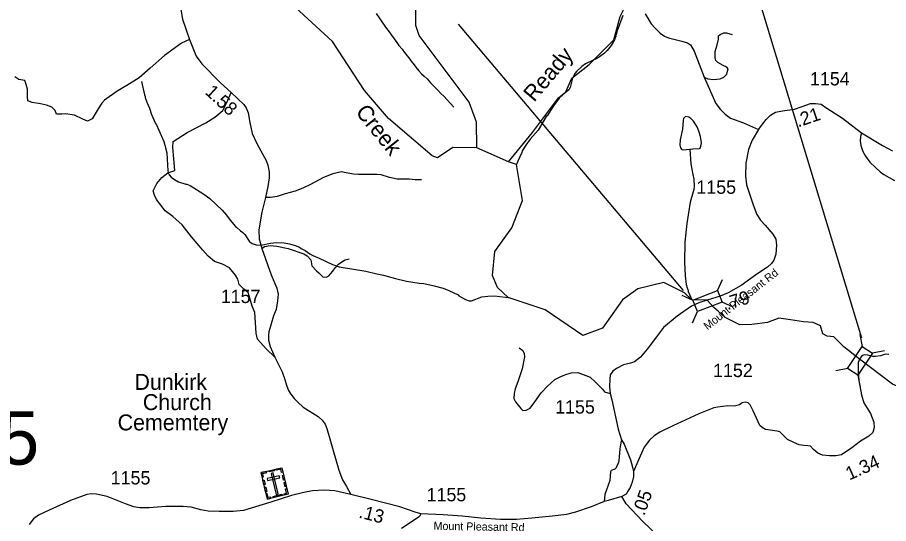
# Model space of a CAD drawing. Extents: x 1248224 to 1454986, y 825081 to 985870.
# Drawn here: x 1300002 to 1308169, y 872533 to 877278 of the extents above; entities that cross this region are included whole.
import ezdxf

# ---------------------------------------------------------------- set-up
doc = ezdxf.new("R2010")
doc.units = 0
for name, color, linetype in [('Exist Cultural Cemetery CELL', 7, 'Continuous'), ('Exist Cultural Church Label', 7, 'Continuous'), ('Exist Hydrographic Creek Single Shore', 7, 'Continuous'), ('Exist Hydrographic Misc Water Feature', 7, 'Continuous'), ('Exist Road Non-System Type 51', 7, 'Continuous'), ('Exist Road Secondary Mileage Hundredths English Label', 7, 'Continuous'), ('Exist Road Secondary Structure Standard Bridge CELL', 7, 'Continuous'), ('Exist Road Secondary Structure Standard Bridge Number Label', 7, 'Continuous'), ('Exist Road Secondary Type 41 Attributed', 7, 'Continuous'), ('Exist Road Secondary Type 51 Attributed', 7, 'Continuous'), ('Exist Road Secondary Type 51 Label', 7, 'Continuous'), ('Exist Road Secondary Type 51 Number Label', 7, 'Continuous')]:
    doc.layers.add(name, color=color, linetype=linetype)

msp = doc.modelspace()

# ---------------------------------------------------------------- linework, layer by layer
at = {"layer": 'Exist Cultural Cemetery CELL'}
for points in [[(1302286.7, 873011), (1302480.3, 873057.3), (1302539.5, 872809.6), (1302345.9, 872763.3)], [(1302296.8, 872968.8), (1302307.8, 872971.5), (1302300.3, 873002.8), (1302339.8, 873012.2), (1302337.2, 873023), (1302286.7, 873011)], [(1302358.7, 873028.2), (1302409.1, 873040.2), (1302411.8, 873029.1), (1302361.4, 873017.1)], [(1302490.5, 873015.1), (1302479.4, 873012.5), (1302472, 873043.8), (1302432.5, 873034.3), (1302429.9, 873045.2), (1302480.4, 873057.2)], [(1302314, 872896.7), (1302303.9, 872938.8), (1302315, 872941.5), (1302325.1, 872899.4)], [(1302342.2, 872954.3), (1302346.6, 872936.1), (1302461.1, 872963.5), (1302456.7, 872981.6)], [(1302399.5, 873007.8), (1302381.4, 873003.5), (1302428.5, 872806.2), (1302446.7, 872810.6)], [(1302496.4, 872941.4), (1302486.3, 872983.5), (1302497.4, 872986.1), (1302507.4, 872944)], [(1302329.6, 872831.3), (1302319.5, 872873.5), (1302330.6, 872876.1), (1302340.7, 872834)], [(1302511.7, 872877.3), (1302501.6, 872919.4), (1302512.7, 872922), (1302522.8, 872879.9)], [(1302507.3, 872801.9), (1302504.6, 872813.1), (1302526, 872818.2), (1302516.6, 872857.5), (1302527.5, 872860.1), (1302539.5, 872809.6)], [(1302378.1, 872771.1), (1302375.4, 872782.2), (1302354, 872777.1), (1302344.6, 872816.4), (1302333.8, 872813.8), (1302345.8, 872763.3)], [(1302399.1, 872787.8), (1302481.7, 872807.6), (1302484.3, 872796.5), (1302401.8, 872776.8)]]:
    msp.add_lwpolyline(points, close=True, dxfattribs=at)
at = {"layer": 'Exist Hydrographic Creek Single Shore'}
for points in [[(1304607.2, 875923.4), (1304830.5, 876199), (1305073.4, 876522.9), (1305142.8, 876580.8), (1305200.7, 876708), (1305362.6, 876835.2), (1305593.9, 877066.6), (1305651.8, 877286.4), (1305744.3, 877471.4), (1305779, 877598.7), (1305779, 877760.6), (1305755.9, 878142.3), (1305755.9, 878558.8), (1305755.9, 878778.5), (1305721.2, 878975.2), (1305721.2, 879160.2), (1305686.5, 879356.9), (1305686.5, 879484.1), (1305744.3, 879831.1), (1305813.7, 880050.9), (1305871.6, 880270.7)], [(1304309.1, 876054.1), (1304084.2, 876058.7), (1303941.2, 875963), (1303891.1, 875980.4), (1303482.2, 876330.1), (1303255.2, 876594), (1302957.1, 877053), (1302532, 877445.5)], [(1306636.7, 874466.4), (1306571.6, 874523.3), (1306531.5, 874558.9), (1306468.8, 874627.1), (1306326.2, 874631), (1306255, 874695.2), (1306062.6, 874794.1), (1305818.9, 874733.2), (1305674, 874629.3), (1305485.9, 874363.9), (1305302.5, 874297.6), (1304950.2, 874537.8), (1304602.2, 874653), (1304504.1, 874747), (1304457.2, 874859.5), (1304479.2, 875082.3), (1304638, 875304.6), (1304736.1, 875560.8), (1304680.5, 875899.4), (1304607.2, 875923.4), (1304309.1, 876054.1)], [(1307897, 874073.3), (1307748.2, 874188.6), (1307654.5, 874282.4), (1307594.8, 874291.6), (1307552.7, 874313.1), (1307532.3, 874386.3), (1307460.9, 874419.2), (1307372.8, 874425.7), (1307249.3, 874442.4), (1307138.8, 874458.8), (1307033.4, 874417.6), (1306886.8, 874399.5), (1306773.2, 874397.8), (1306636.7, 874466.4)], [(1309154.5, 873303.6), (1309141.3, 873330.9), (1308897.3, 873588.6), (1308830.3, 873606.4), (1308585.6, 873596.3), (1308575.8, 873602.6), (1308466.6, 873740.7), (1308388.7, 873762), (1308206.5, 873839.3), (1307897, 874073.3)]]:
    msp.add_lwpolyline(points, dxfattribs=at)
at = {"layer": 'Exist Hydrographic Misc Water Feature'}
for points in [[(1304309.1, 876054.1), (1304307.2, 876297.2), (1304236.1, 876482.4), (1303767.1, 877109), (1303736.1, 877201.5), (1303743.1, 877867.7), (1303674.1, 878479.7), (1303649.1, 878503.2), (1303651.1, 878588.5), (1303589.1, 878763.8), (1303637.1, 879396.4), (1303337.6, 879538.2), (1303277.1, 879679.4), (1303282, 879895.9), (1303361.1, 880094.6), (1303645.1, 880463.1), (1303932, 880956.4), (1304359.1, 881397.5)], [(1305677.6, 877295.2), (1305625.6, 877152.8), (1305616.5, 877115.1), (1305610.3, 877109.2), (1305612.1, 877101.2), (1305599.2, 877069.5), (1305567.7, 877014.5), (1305530.3, 876967.6), (1305505.6, 876944.4), (1305458.6, 876907.7), (1305440.2, 876896.3), (1305326.7, 876841.5), (1305294, 876818.5), (1305244.7, 876771.9), (1305232.2, 876756.3), (1305206.9, 876709.1), (1305184.4, 876621.7), (1305171.8, 876598.1), (1305114.4, 876551.8), (1305081.6, 876520.7), (1305027.6, 876450.3), (1304968.9, 876356.1), (1304960.7, 876348.3), (1304885, 876222.5), (1304810.6, 876136.7), (1304769.1, 876081.9), (1304735.6, 876026.9), (1304731.1, 876011.1), (1304692.8, 875932.1), (1304680.5, 875899.4)], [(1301164.4, 876677.9), (1301192.9, 876553.1), (1301200.5, 876536.9), (1301200.2, 876528.9), (1301214.9, 876484.5), (1301239.3, 876427.8), (1301259.7, 876367.2), (1301295.4, 876284.2), (1301304.9, 876269.9), (1301327.6, 876221.3), (1301374.7, 876116.1), (1301385.6, 876079.7), (1301401.6, 876007.3), (1301412.9, 875839), (1301418.2, 875814.8), (1301425.9, 875802.6), (1301443.4, 875782.1), (1301474.6, 875757.2), (1301514, 875736.1), (1301581.5, 875714.2), (1301589.5, 875713.9), (1301621.1, 875701), (1301750.9, 875621.3), (1301805.8, 875579.7), (1301922.8, 875472.4), (1301963.5, 875423.2), (1301996.2, 875376.3), (1302046.5, 875316.9), (1302060.3, 875308.5), (1302093.4, 875277.5), (1302116.9, 875260.8), (1302134.4, 875242.3), (1302174.7, 875181.2), (1302182.5, 875172.9), (1302204.1, 875160.3), (1302241.8, 875147.3), (1302285.7, 875144), (1302374.3, 875163.4), (1302430.5, 875167.8), (1302502.4, 875165.7), (1302554.1, 875154.3), (1302607.7, 875138.7), (1302645.3, 875123.6), (1302661, 875111.2), (1302698.5, 875092.1), (1302743.6, 875060.8), (1302771.2, 875046), (1302830.5, 875022.3), (1302956.8, 874960.7), (1303020.2, 874938.9), (1303267.3, 874899.7), (1303370.6, 874874.7), (1303434.3, 874862.9), (1303545.4, 874829.7), (1303648.8, 874806.7), (1303768.3, 874787.2), (1303812.2, 874783.9), (1303907.7, 874763.2), (1303995, 874738.7), (1304046.5, 874719.2), (1304133.3, 874676.7), (1304141.1, 874668.5), (1304202.2, 874634.8), (1304235.9, 874621.7), (1304259.8, 874621.1), (1304356.9, 874658.2), (1304413.1, 874666.6), (1304477.2, 874666.7), (1304501.1, 874664.1), (1304602.2, 874653)], [(1306304.7, 876044), (1306332.7, 876046.7), (1306396.8, 876048.9), (1306402.9, 876052.7), (1306409.4, 876070.4), (1306414.3, 876102.3), (1306406, 876162.5), (1306391.4, 876211), (1306374.5, 876251.4), (1306340, 876304.4), (1306316.7, 876329.1), (1306297, 876341.6), (1306269.3, 876350.4), (1306261.2, 876346.6), (1306246.7, 876329.1), (1306242.2, 876311.3), (1306235.9, 876231.4), (1306215, 876130.1), (1306211.6, 876080.2), (1306217, 876056.1), (1306230.5, 876039.7), (1306244.4, 876037.2), (1306304.7, 876044)], [(1306304.7, 876044), (1306316.7, 875905.3), (1306333.9, 875804.8), (1306344.7, 875760.5), (1306346.9, 875696.4), (1306342, 875664.5), (1306308.6, 875545.6), (1306277, 875346.5), (1306260.1, 875171.1), (1306256.8, 874983.2), (1306263.3, 874857.1), (1306272.9, 874774.8), (1306280.1, 874742.6), (1306291.4, 874718.3), (1306291.2, 874710.3), (1306326.2, 874631)]]:
    msp.add_lwpolyline(points, dxfattribs=at)
at = {"layer": 'Exist Road Non-System Type 51'}
for points in [[(1303366.2, 877315), (1303401, 877264.1), (1303453.3, 877186.8), (1303486.2, 877142.1), (1303509.6, 877111.4), (1303534.7, 877076.9), (1303558.1, 877044.2), (1303579.4, 877015.7), (1303608.7, 876981.1), (1303631.8, 876948.4), (1303657.2, 876917.9), (1303680.4, 876885.2), (1303694, 876866.9), (1303721.2, 876834.4), (1303738.8, 876812), (1303765.9, 876777.3), (1303791.3, 876748.7), (1303814.9, 876726), (1303842.2, 876701.5), (1303875.5, 876664.6), (1303900.8, 876640.1), (1303943.8, 876597), (1303973.2, 876564.4), (1304000.7, 876539.6), (1304092.3, 876437.5)], [(1306438.8, 876719.5), (1306474.3, 876703.1), (1306526.6, 876695.3), (1306591.9, 876703.1), (1306625.9, 876718.8), (1306652, 876747.6), (1306659.9, 876773.8), (1306665.1, 876797.3), (1306652, 876810.4), (1306618.1, 876828.7), (1306568.4, 876854.9), (1306550.1, 876873.2), (1306544.9, 876899.4), (1306544.9, 876959.5), (1306563.2, 877022.3), (1306576.2, 877074.7), (1306576.2, 877106), (1306591.9, 877119.1), (1306623.3, 877132.2), (1306649.4, 877132.2), (1306701.7, 877119.1)], [(1301614.6, 877069.7), (1301540.8, 877035.5), (1301380.6, 876921.3), (1301247.1, 876802.3), (1301142.7, 876712.5), (1301028.7, 876639.6), (1300936.4, 876586.2), (1300817.5, 876503.6), (1300793.3, 876474.4), (1300759.3, 876421), (1300703.5, 876328.7), (1300659.8, 876304.4), (1300616.1, 876323.9), (1300538.4, 876360.3), (1300453.5, 876374.9), (1300417.9, 876372.4), (1300369.4, 876372.4), (1300354.8, 876404), (1300325.7, 876438), (1300274.7, 876455), (1300218.9, 876469.5), (1300141.3, 876479.2), (1300100, 876496.2), (1300097.6, 876537.5), (1300097.6, 876605.5), (1300085.4, 876649.3), (1300070.9, 876685.7), (1300015.1, 876695.4), (1299978.7, 876722.1)], [(1302416.2, 874093.5), (1302333.7, 874171.1), (1302282.7, 874229.3), (1302253.6, 874263.3), (1302241.5, 874319.2), (1302226.9, 874511.1), (1302202.6, 874571.8), (1302176, 874669), (1302166.2, 874698.1), (1302125, 874729.7), (1302081.3, 874775.8), (1302069.2, 874824.4), (1302047.3, 874863.3), (1301991.5, 874931.3), (1301924.1, 874963.6), (1301851.3, 874990.3), (1301790.6, 875041.3), (1301742, 875097.2), (1301635.3, 875221.1), (1301545.4, 875332.8), (1301458.1, 875410.5), (1301387.7, 875466.4), (1301305.7, 875572), (1301286.3, 875610.9), (1301274.2, 875652.2), (1301310.6, 875720.2), (1301356.7, 875778.5), (1301412.5, 875819.8), (1301478, 875841.6), (1301468.3, 875950.9), (1301458.6, 876057.8), (1301461.1, 876116.1), (1301594.5, 876198.7), (1301769.3, 876288.5), (1301854.2, 876342), (1301927, 876405.1), (1301965.9, 876480.4), (1302007.1, 876572.7)], [(1303790.3, 875756.7), (1303732, 875754.2), (1303673.8, 875761.5), (1303620.4, 875761.5), (1303562.1, 875761.5), (1303491.7, 875776.1), (1303411.6, 875802.8), (1303370.4, 875805.2), (1303319.4, 875805.2), (1303266, 875805.2), (1303200.5, 875805.2), (1303152, 875807.7), (1303067, 875824.7), (1303040.3, 875829.5), (1302960.2, 875812.5), (1302872.8, 875778.5), (1302749.1, 875712.9), (1302678.7, 875678.9), (1302605.9, 875649.8), (1302511.2, 875623.1), (1302436, 875598.8), (1302375.3, 875589.1), (1302329.2, 875591.5)], [(1302293.9, 875110.5), (1302319.6, 875131.3), (1302370.5, 875141), (1302433.6, 875133.7), (1302540.4, 875111.9), (1302688.5, 875060.9), (1302720, 875043.9), (1302754, 875005), (1302761.3, 874949.1), (1302805, 874903), (1302831.7, 874881.1), (1302865.7, 874847.1), (1302897.2, 874842.3), (1302921.5, 874856.8), (1302957.9, 874900.6), (1302979.7, 874929.7), (1303013.7, 874963.7), (1303042.8, 874988), (1303074.4, 875005), (1303113.2, 875014.7)], [(1304706.1, 874181.4), (1304740.1, 874154.7), (1304752.2, 874128), (1304754.6, 874096.4), (1304735.2, 873984.7), (1304693.9, 873863.2), (1304667.3, 873795.2), (1304660, 873751.5), (1304657.5, 873705.3), (1304672.1, 873673.8), (1304720.6, 873610.6), (1304740.1, 873593.6), (1304771.6, 873596), (1304808, 873615.5), (1304851.7, 873673.8), (1304912.4, 873758.8), (1304970.6, 873821.9), (1305041, 873885.1), (1305089.6, 873909.4), (1305135.7, 873926.4), (1305193.9, 873945.8), (1305257, 873948.2), (1305329.8, 873921.5), (1305371.1, 873906.9), (1305417.2, 873863.2), (1305487.6, 873792.8), (1305507, 873768.5), (1305558, 873753.9)], [(1305666.4, 873317.5), (1305659.2, 873290.7), (1305649.4, 873234.9), (1305644.6, 873157.2), (1305637.3, 873103.7), (1305622.8, 873074.6), (1305615.5, 873055.2), (1305603.3, 873043), (1305569.4, 873030.9), (1305562.1, 873018.7), (1305559.6, 872977.4), (1305557.2, 872936.1), (1305508.7, 872807.4), (1305503.8, 872739.4)]]:
    msp.add_lwpolyline(points, dxfattribs=at)
at = {"layer": 'Exist Road Secondary Structure Standard Bridge CELL'}
for p, q in [((1306565.9, 874717.4), (1306611.4, 874821)), ((1306231.1, 874673.4), (1306334.7, 874627.9)), ((1306607, 874611.9), (1306710.6, 874566.5)), ((1306331.3, 874416.4), (1306376.8, 874520)), ((1307899.8, 874305.6), (1307922.2, 874194.7)), ((1308129.5, 874152.9), (1308018.6, 874130.6)), ((1307786.7, 873987.1), (1307675.7, 873964.7)), ((1307880.9, 873924.4), (1307903.3, 873813.5))]:
    msp.add_line(p, q, dxfattribs=at)
for points in [[(1306334.7, 874627.9), (1306565.7, 874717.9), (1306607.7, 874610), (1306376.8, 874520)], [(1308018.6, 874130.6), (1307881.4, 873924.1), (1307784.9, 873988.2), (1307922.2, 874194.7)]]:
    msp.add_lwpolyline(points, close=True, dxfattribs=at)
at = {"layer": 'Exist Road Secondary Structure Standard Bridge Number Label'}
for p, q in [((1307919.3, 874272), (1306898.1, 877637.1)), ((1306245.8, 874716.8), (1304137.2, 877215))]:
    msp.add_line(p, q, dxfattribs=at)
at = {"layer": 'Exist Road Secondary Type 41 Attributed'}
for points in [[(1307897, 874073.3), (1307885.4, 874043.2), (1307885, 873954.8), (1307890.5, 873874.7), (1307916.2, 873739.5), (1307936.5, 873666.2), (1308000.3, 873564.4), (1308031.5, 873484.3), (1308032.8, 873432.7), (1308020.6, 873387.9), (1307984, 873354), (1307907.2, 873306.9), (1307823.4, 873243.2), (1307728.5, 873178), (1307675.6, 873168.5), (1307615.9, 873168.5), (1307548.1, 873174), (1307507.4, 873194.3), (1307466.7, 873226.9), (1307438.2, 873258.1), (1307412.4, 873263.5), (1307374.5, 873264.9), (1307331.1, 873270.3), (1307279.5, 873292.1), (1307222.5, 873320.6), (1307177.8, 873365.4), (1307150.7, 873392.5), (1307125.6, 873399), (1307060.5, 873408.5), (1307015.7, 873416.6), (1306984.5, 873432.9), (1306962.8, 873453.3), (1306900.5, 873589), (1306870.6, 873646), (1306853, 873663.7), (1306825.9, 873671.8), (1306797.4, 873666.4), (1306773, 873647.4), (1306722.8, 873635.2), (1306661.7, 873636.5), (1306569.5, 873625.6), (1306530.2, 873617.5), (1306389.1, 873561.8), (1306148.1, 873448.6), (1306024.6, 873390.2), (1305970.4, 873356.3), (1305928.3, 873314.2), (1305876.8, 873249.1), (1305826.6, 873137.7), (1305776.6, 873022.7)], [(1308170.7, 874119.4), (1308140.8, 874120.8), (1308092, 874105.9), (1308047.3, 874099.1), (1308021.5, 874100.4), (1307975.4, 874112.6), (1307941.5, 874115.4), (1307917, 874104.5), (1307897, 874073.3)]]:
    msp.add_lwpolyline(points, dxfattribs=at)
at = {"layer": 'Exist Road Secondary Type 51 Attributed'}
for points in [[(1301530.1, 877369.7), (1301550.9, 877261.7), (1301614.6, 877069.7), (1301678.2, 876914), (1301730.2, 876843.7), (1301907.1, 876664.1), (1302007.1, 876572.7), (1302123.9, 876463.1), (1302147.3, 876430.6), (1302165.5, 876385), (1302181.1, 876292.6), (1302204.3, 876189.1), (1302249.9, 876088.9), (1302333.1, 875935.3), (1302351, 875893.3), (1302362.7, 875829.5), (1302364, 875773.6), (1302349.7, 875692.9), (1302329.2, 875591.5), (1302293.8, 875452.1), (1302274.4, 875343.5), (1302265.3, 875282.4), (1302267.9, 875201.7), (1302293.9, 875110.5), (1302382.3, 874865.2), (1302434.3, 874738.9), (1302446, 874684.9), (1302442.1, 874621.1), (1302427.8, 874539.1), (1302404.4, 874479.3), (1302358.8, 874332.2), (1302355.1, 874296.5), (1302356.4, 874252.2), (1302373.3, 874193.7), (1302416.2, 874093.5), (1302485.2, 873955.5), (1302507.1, 873893.8), (1302526.7, 873822.2), (1302542.3, 873779.2), (1302564.4, 873745.4), (1302596.9, 873706.3), (1302630.7, 873672.5), (1302682.7, 873624.3), (1302823.2, 873535.8), (1302859.4, 873503.9), (1302888, 873464.8), (1302902.3, 873424.5), (1302938.7, 873304.8), (1303014, 873033.4), (1303050.4, 872943.5), (1303086.7, 872881.5), (1303127, 872804.7)], [(1305888.7, 877312.7), (1305942.9, 877217.7), (1305980.6, 877176.3), (1306028, 877131.5), (1306067.4, 877101.7), (1306106.7, 877085.4), (1306230.1, 877054.2), (1306283, 877039.2), (1306311.5, 877020.2), (1306346.8, 876961.9), (1306438.8, 876719.5), (1306548.6, 876469.7), (1306589, 876417.4), (1306637.8, 876371.2), (1306688, 876334.6), (1306810.1, 876288.4), (1306951.2, 876227.4)], [(1306951.2, 876227.4), (1307022.9, 876320.3), (1307063.6, 876362.4), (1307109.7, 876389.6), (1307174.8, 876403.1), (1307288.7, 876416.7), (1307360.6, 876443.8), (1307436.6, 876469.6), (1307482.7, 876472.4), (1307535.6, 876465.6), (1307589.8, 876427.6), (1307737.7, 876332.5), (1307914, 876195.4)], [(1306951.2, 876227.4), (1306891.6, 876128.5), (1306856.4, 876038.9), (1306832, 875912), (1306826.5, 875789.8), (1306838.7, 875708.4), (1306899.8, 875519.7), (1306934.9, 875429.6), (1306967.5, 875376.7), (1307013.6, 875329.2), (1307085.5, 875247.7), (1307112.6, 875200.2), (1307119.4, 875144.5), (1307111.3, 875059), (1307093.7, 875002.6), (1307072, 874971.4), (1307035.3, 874937.5), (1306935, 874870.9), (1306785.8, 874765.1), (1306664.1, 874697.7), (1306589.5, 874663.8), (1306468.8, 874627.1)], [(1307914, 876195.4), (1307904.7, 876161.2), (1307902, 876121.8), (1307908.8, 876078.4), (1307927.4, 876022), (1307951.8, 875975.9), (1307993.9, 875920.2), (1308045.4, 875871.4), (1308088.8, 875830.6), (1308125.4, 875804.8), (1308223.1, 875750.5)], [(1307914, 876195.4), (1308111.9, 876076), (1308205.8, 876026.8)], [(1306468.8, 874627.1), (1306390.2, 874602.7), (1306322.3, 874570.1), (1306186.7, 874476.4), (1306058.5, 874371.3), (1305992, 874284.4), (1305906.6, 874167.7), (1305844.2, 874091.7), (1305787.6, 874050.2), (1305751, 874036.6), (1305684.5, 874020.3), (1305619.4, 873987.7), (1305585.5, 873960.6), (1305559.7, 873926.6), (1305555.6, 873887.3), (1305552.9, 873816.7), (1305558, 873753.9), (1305574.6, 873694.5), (1305635.6, 873418.4), (1305666.4, 873317.5), (1305691.2, 873277.2), (1305749.4, 873131.3), (1305769.8, 873063.4), (1305776.6, 873022.7)], [(1305776.6, 873022.7), (1305778.9, 872975.4), (1305765.4, 872921.1), (1305747.7, 872870.9), (1305726, 872835.6), (1305708.4, 872808.5), (1305667.7, 872788.1)], [(1303127, 872804.7), (1302976.9, 872841.1), (1302878.7, 872845.2), (1302767.5, 872839.8), (1302688.8, 872823.5), (1302572.1, 872797.7), (1302378.2, 872735.3), (1302121.2, 872656.5), (1302024.9, 872645.7), (1301894.7, 872645.7), (1301790.2, 872651.1), (1301722.4, 872660.6), (1301631.5, 872687.8), (1301556.9, 872694.6), (1301392.3, 872693.2), (1301239, 872682.3), (1301149.5, 872681), (1301095.3, 872690.5), (1301015.2, 872717.6), (1300843, 872788.2), (1300745.3, 872808.6), (1300693.8, 872812.6), (1300651.7, 872805.9), (1300499, 872748.1), (1300299.6, 872659.9), (1300200.6, 872611), (1300154.5, 872577.1), (1300111.1, 872524.2)], [(1303783.6, 872624.5), (1303732.5, 872640.4), (1303587.3, 872690.6), (1303317.4, 872759.9), (1303127, 872804.7)], [(1305667.7, 872788.1), (1305539.9, 872749), (1305503.8, 872739.4), (1305380.5, 872689.7), (1305234, 872640.8), (1305149.9, 872619.1), (1305018.4, 872601.4), (1304825.8, 872583.8), (1304680.2, 872570.2), (1304529.6, 872572.9), (1304346.5, 872585.2), (1304170.2, 872601.5), (1303993.8, 872616.4), (1303783.6, 872624.5)], [(1306016.6, 872408.6), (1305863.3, 872557.2), (1305709.9, 872718.9), (1305667.7, 872788.1)], [(1303783.6, 872624.5), (1303770.8, 872600.8), (1303712.4, 872558), (1303603.5, 872485.9)]]:
    msp.add_lwpolyline(points, dxfattribs=at)

# ---------------------------------------------------------------- texts
at = {"layer": 'Exist Cultural Church Label'}
for s, p in [('Dunkirk', (1301099.5, 873786.7)), ('Church', (1301178.3, 873596.7)), ('Cememtery', (1300942, 873406.7))]:
    msp.add_text(s, height=150, dxfattribs=at).set_placement(p)
at = {"layer": 'Exist Hydrographic Creek Single Shore'}
for s, rotation, p in [('Ready', 49.70785, (1304846.4, 876477.7)), ('Creek', 308.65981, (1303165.5, 876389.1))]:
    msp.add_text(s, height=150, rotation=rotation, dxfattribs=at).set_placement(p)
at = {"layer": 'Exist Road Secondary Mileage Hundredths English Label'}
for s, rotation, p in [('1.58', 317.16951, (1301753.9, 876568.6)), ('.21', 18.75564, (1307321.5, 876246.6)), ('.79', 17.25469, (1306658, 874533.3)), ('1.34', 23.97963, (1307801.2, 872936.4)), ('.05', 70.65546, (1305879.9, 872601)), ('.13', 345.61465, (1303195.8, 872590.5))]:
    msp.add_text(s, height=125, rotation=rotation, dxfattribs=at).set_placement(p)
at = {"layer": 'Exist Road Secondary Type 51 Label'}
for rotation, p in [(38.14281, (1306471.7, 874343.6)), (359.00436, (1303903, 872475.2))]:
    msp.add_text('Mount Pleasant Rd', height=75, rotation=rotation, dxfattribs=at).set_placement(p)
at = {"layer": 'Exist Road Secondary Type 51 Number Label'}
for s, height, p in [('1154', 125, (1307432.5, 876640.3)), ('1155', 125, (1306367.4, 875624.6)), ('1157', 125, (1301909.2, 874600.4)), ('1152', 125, (1306524.1, 873906.5)), ('1155', 125, (1305043.7, 873564.6)), ('1155', 500, (1298718.7, 873085.7)), ('1155', 125, (1300877, 872899.9)), ('1155', 125, (1303838.1, 872741.8))]:
    msp.add_text(s, height=height, dxfattribs=at).set_placement(p)

doc.saveas('drawing.dxf')
